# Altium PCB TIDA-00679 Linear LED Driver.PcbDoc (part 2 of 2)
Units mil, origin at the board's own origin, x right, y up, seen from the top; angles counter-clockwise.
Board outline 4400 x 2430 mil, 2 copper layers (Top Layer, Bottom Layer), stack 62 mil thick; 157 components, 72 nets, 421 pads, 393 vias.
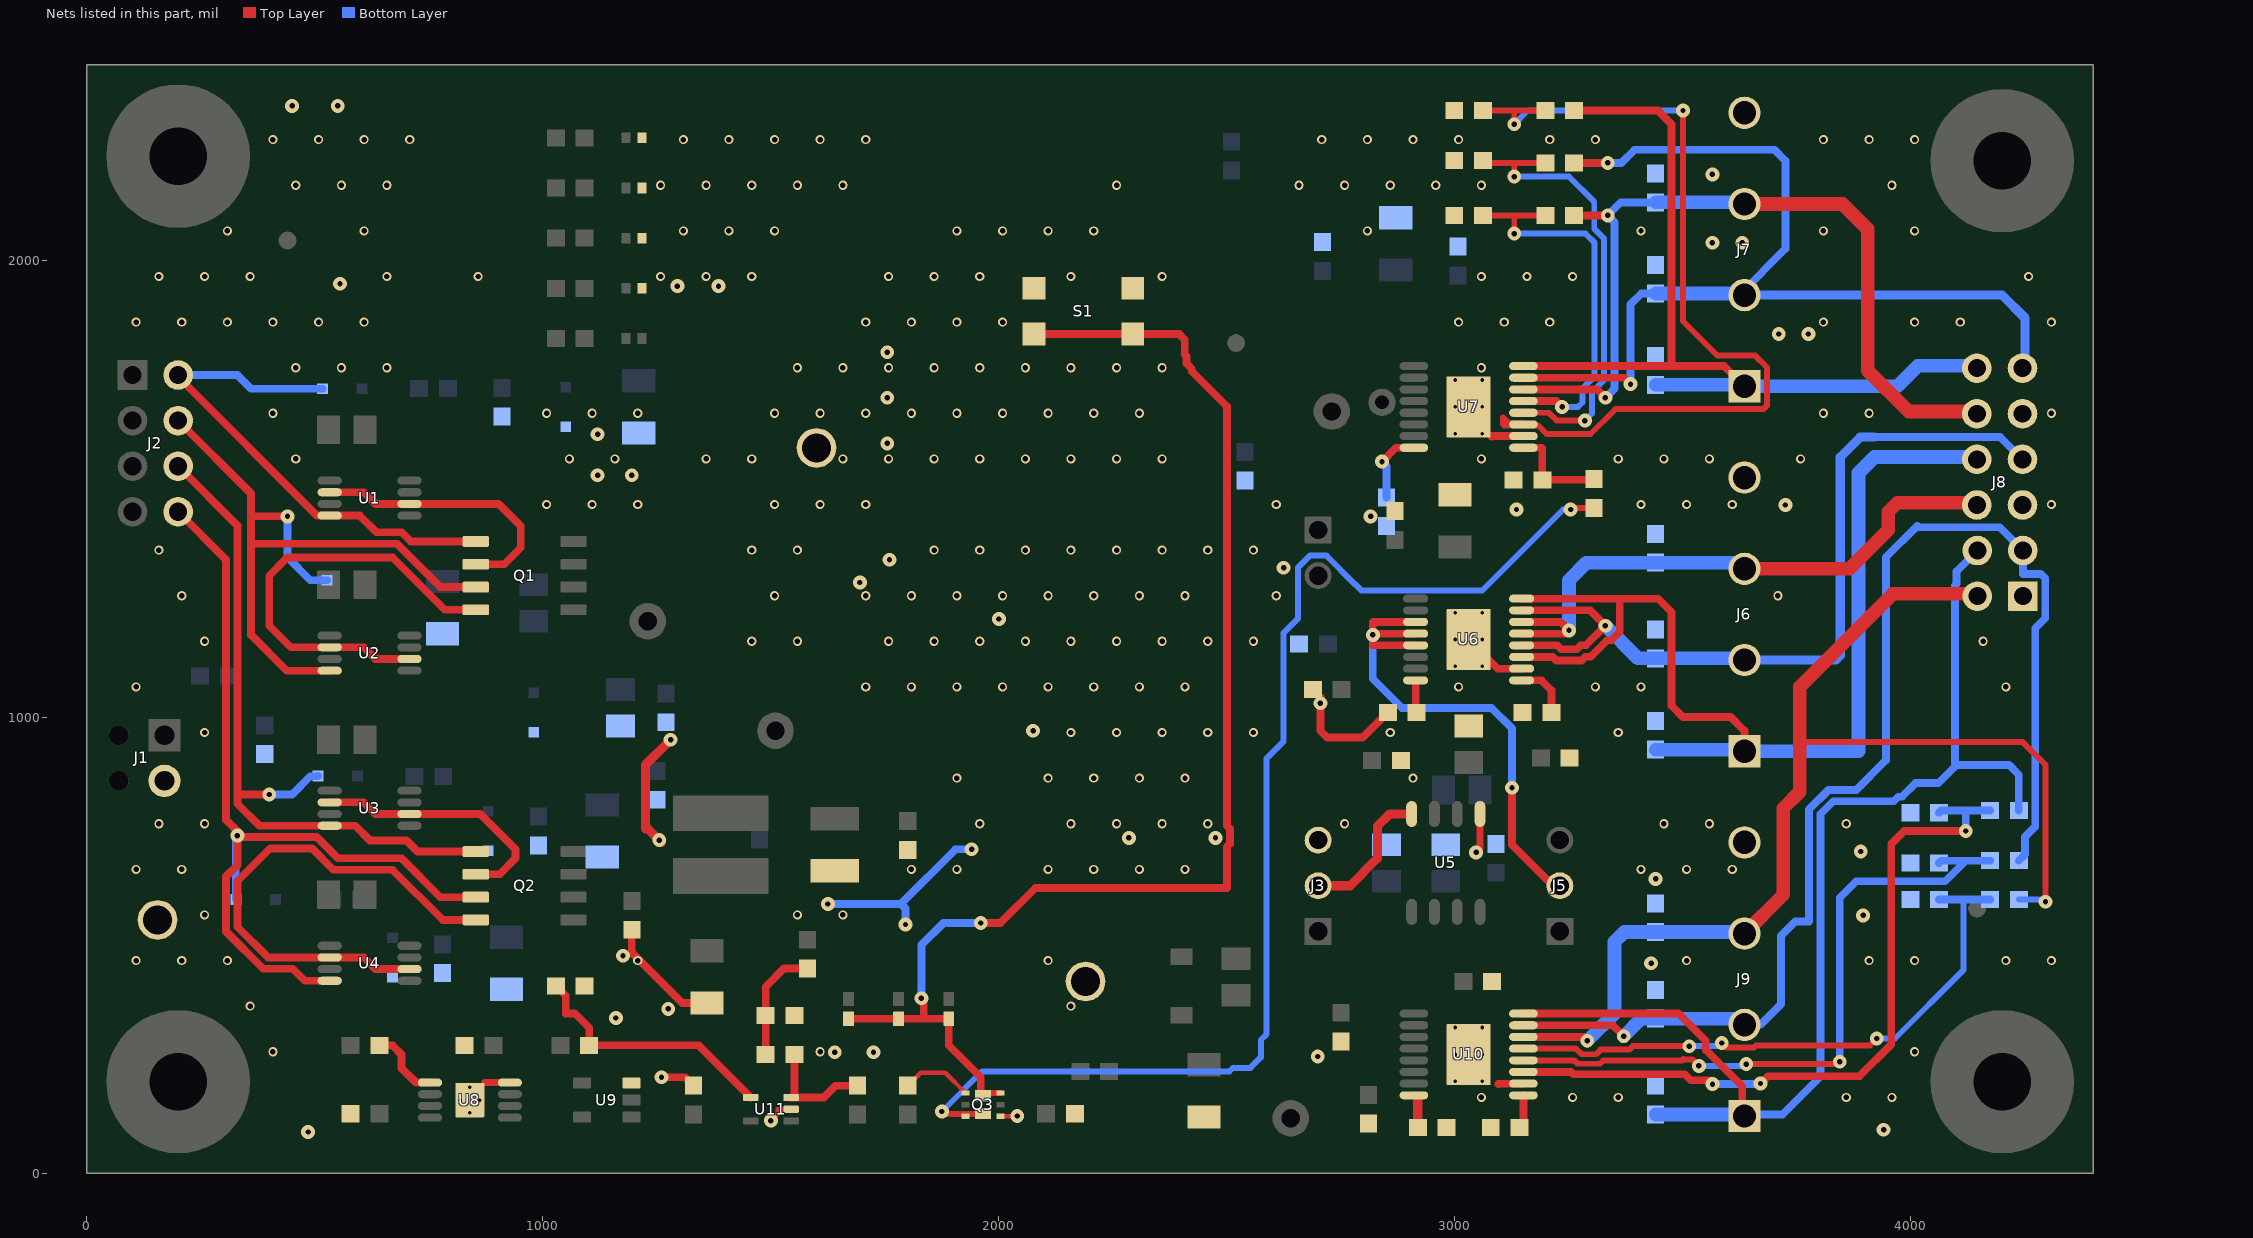
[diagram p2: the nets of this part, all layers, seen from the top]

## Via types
v1: diameter 20, hole 12, Top Layer to Bottom Layer, tented both sides, 246 vias
v2: diameter 30.32, hole 11.81, Top Layer to Bottom Layer, tented both sides, 123 vias
v3: diameter 15.75, hole 7.87, Top Layer to Bottom Layer, 18 vias
v4: diameter 19.68, hole 7.87, Top Layer to Bottom Layer, 4 vias
v5: diameter 30.32, hole 11.81, Top Layer to Bottom Layer, 2 vias

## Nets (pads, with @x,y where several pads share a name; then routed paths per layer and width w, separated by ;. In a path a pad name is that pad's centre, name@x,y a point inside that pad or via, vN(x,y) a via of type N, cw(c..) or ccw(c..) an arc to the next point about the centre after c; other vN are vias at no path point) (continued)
NetJ3_2: J3.2 U5.4 | length 311.2
  Top Layer w20: J3.2@2700,630 2770,630 2830,690 2830,760 2857.28,787.28 U5.4@2905,787.28
NetJ5_2: J5.2 U6.3 U6.4 U6.5 | length 1175.9
  Top Layer w17: U6.5@2913.86,1157.2 2820,1157.2 v2(2820,1180) v2@2820,1182.8 ; U6.4@2913.86,1182.8 v2@2820,1182.8 ; U6.3@2913.86,1208.39 2820.72,1208.39 2820,1207.67 v2@2820,1182.8 ; v2(3125,845) 3125,720 3215,630 J5.2@3230,630
  Bottom Layer w17: v2(2820,1180) 2820,1083.7 2883.7,1020 3080,1020 3125,975 v2(3125,845)
NetQ1_2: Q1.2 U1.2 U1.6 | length 610.5
  Top Layer w17: U1.2@532.4,1492.8 607.2,1492.8 632.8,1467.2 U1.6@707.6,1467.2 902.8,1467.2 951.14,1418.86 951.14,1371.14 915,1335 Q1.2@852.72,1335
NetQ1_4: Q1.4 U2.2 U2.6 | length 964.7
  Top Layer w17: U2.6@707.6,1127.2 632.8,1127.2 607.2,1152.8 U2.2@532.4,1152.8 447.2,1152.8 400,1200 400,1310 440,1350 670,1350 785,1235 Q1.4@852.72,1235
NetQ2_2: Q2.2 U3.2 U3.6 | length 572
  Top Layer w17: U3.2@532.4,812.8 607.2,812.8 632.8,787.2 U3.6@707.6,787.2 862.8,787.2 940,710 940,690 905,655 Q2.2@852.72,655
NetQ2_4: Q2.4 U4.2 U4.6 | length 1133.5
  Top Layer w17: U4.6@707.6,447.2 632.8,447.2 607.2,472.8 U4.2@532.4,472.8 397.2,472.8 330,540 330,640 401.87,711.87 493.57,711.87 540.31,665.13 670,665.13 780.13,555 Q2.4@852.72,555
NetQ3_6: Q3.6 Q3.7 R20.1 | length 2724.5
  Top Layer w13: v2(1875,135) 1880.87,129.13 1965,129.13 Q3.7@1965,130.79 ; v2(3253.7,1455) 3257.2,1458.5 R20.1@3305,1458.5
  Bottom Layer w13: v2@1870,140 v2(1875,135) 1962.97,222.97 2505.63,222.97 2513.28,230.63 2551.31,230.63 2574.37,253.69 2574.37,291.72 2587.13,304.47 2587.13,909.47 2624.44,946.79 2624.44,1184.65 2656.1,1216.31 2656.1,1328.18 2681.82,1353.9 2718.18,1353.9 2780.63,1291.46 2781.19,1291.46 2795.53,1277.13 3059.47,1277.13 3237.35,1455 v2(3253.7,1455)
NetR16_2: R16.2 U6.8 | length 71.3
  Top Layer w17: U6.8@2913.86,1080.43 2913.86,1012.07 R16.2@2915.92,1010
NetR17_2: R17.2 U7.8 | length 169.1
  Top Layer w17: v2(2840,1560) 2870.43,1590.43 U7.8@2913.86,1590.43
  Bottom Layer w17: v2(2840,1560) 2850,1550 R17.2@2850,1481.5
NetR18_2: R18.2 U6.9 | length 122.9
  Top Layer w17: U6.9@3146.14,1080.43 3189.57,1080.43 3211.5,1058.5 R18.2@3211.5,1010
NetR19_2: R19.2 R20.2 U7.9 | length 226.9
  Top Layer w17: U7.9@3146.14,1590.43 3190,1590.43 3191.5,1588.94 R19.2@3191.5,1520 R20.2@3303.5,1520
NetR21_1: R21.1 R22.2 U7.13 | length 861.9
  Top Layer w13: R22.2@3061.5,2100 3130,2100 ; v2(3130,2060) 3130,2100 ; R21.1@3198.5,2100 3130,2100
  Top Layer w17: U7.13@3150.08,1692.8 3222.2,1692.8 v2(3235,1680)
  Bottom Layer w13: v2(3130,2060) 3286.42,2060 3306.25,2040.16 3306.25,1747.54 3279.59,1720.88 3279.59,1689.59 3270,1680 v2(3235,1680)
NetR23_1: R23.1 R24.2 U7.12 | length 1015.5
  Top Layer w13: R24.2@3061.5,2220 3066.5,2215 3130,2215 ; v2(3130,2185) 3130,2215 ; U7.12@3150.08,1667.2 3206.03,1667.2 3222.77,1650.47 3284.53,1650.47 v2(3285,1650) ; R23.1@3198.5,2215 3130,2215
  Bottom Layer w13: v2(3130,2185) 3250,2185 3305.47,2129.53 3305.47,2070.47 3327.13,2048.81 3327.13,1738.89 3300.47,1712.23 3300.47,1665.47 v2(3285,1650)
NetR25_1: R25.1 R26.2 U7.11 | length 2006.6
  Top Layer w13: R26.2@3061.5,2330 3130,2330 ; v2(3130,2300) 3130,2330 ; U7.11@3150.08,1641.61 3152.44,1643.97 3117.82,1643.97 3104.82,1656.97 3104.82,1642.52 3108.08,1639.26 3182.34,1639.26 3201.13,1620.47 3297.23,1620.47 3351.96,1675.19 3676.18,1675.19 3684.6,1683.61 3684.6,1766.39 3658.54,1792.44 3575.77,1792.44 3500,1868.21 v2(3500,2330) ; R25.1@3198.5,2330 3130,2330
  Bottom Layer w13: v2(3130,2300) 3160,2330 v2(3500,2330)
NetR27_1: R27.1 U8.5 | length 162.3
  Top Layer w17: R27.1@641.5,280 670,280 690,260 690,230 721.61,198.39 U8.5@752.4,198.39
NetR32_1: R32.1 R33.2 R37.1 | length 256.6
  Top Layer w17: R37.1@1488.5,260 1488.5,350 1488.5,408.5 1528.5,448.5 R32.1@1580,448.5
NetR34_1: R34.1 R35.2 U11.4 | length 573.6
  Top Layer w17: R35.2@1028.5,410 1050,388.5 1050,350 1070,350 1101.5,318.5 R34.1@1101.5,280 1341.3,280 U11.4@1455.71,165.59
NetR36_2: R36.2 U10.8 | length 71.2
  Top Layer w20: U10.8@2913.86,169.29 2918.5,164.65 R36.2@2918.5,100
NetR37_2: R37.2 R39.2 U11.3 | length 253.8
  Top Layer w17: R37.2@1551.5,260 1551.5,172.8 U11.3@1544.29,165.59 1615.59,165.59 1641.5,191.5 R39.2@1690,191.5
NetR38_2: R38.2 U10.9 | length 74
  Top Layer w17: R38.2@3141.5,100 3150.08,108.58 U10.9@3150.08,170.43
NetR40_1: R40.1 R41.2 U10.13 | length 1321.6
  Top Layer w13: U10.13@3150.08,272.8 3265.44,272.8 3277.77,260.47 3309.53,260.47 3319.53,270.47 3382.23,270.47 3389.92,278.16 v2(3513.77,278.16) ; v2(3585,285) 3594.81,275.19 3655.42,275.19 3660.23,280 3910,280 v2(3925,295)
  Bottom Layer w13: v2(3513.77,278.16) 3578.16,278.16 v2(3585,285) ; v2(3925,295) 3965,295 4115,445 4115,600
  Bottom Layer w17: R41.2@4061.5,600 4115,600 R40.1@4173.5,600
NetR42_1: R42.1 R43.2 U10.12 | length 1494.6
  Top Layer w13: U10.12@3150.08,247.2 3261.51,247.2 3269.12,239.59 3318.18,239.59 3325.79,247.2 3498.18,247.2 3500.57,249.59 3501.53,248.63 3521.37,248.63 v2(3535,235) ; v2(3638.89,238.89) 3838.89,238.89 v2(3843.89,243.89)
  Bottom Layer w13: v2(3535,235) 3635,235 v2(3638.89,238.89)
  Bottom Layer w17: v2(3843.89,243.89) 3843.89,603.89 3880,640 4075,640 4120,685 ; R43.2@4061.5,680 4066.5,685 4120,685 ; R42.1@4173.5,685 4120,685
NetR44_1: R44.1 R45.2 U10.11 | length 1627.4
  Top Layer w17: U10.11@3150.08,221.61 3254.75,221.61 3259.65,216.72 3503.79,216.72 3517.05,203.47 3556.36,203.47 v2(3564.75,195.08) ; v2(3669.97,196.21) 3686.12,212.36 3886.95,212.36 3956.53,281.94 3956.53,721.53 3985,750 v2(4120,750)
  Bottom Layer w17: v2(3564.75,195.08) 3668.84,195.08 v2(3669.97,196.21) ; R45.2@4061.5,790 4066.5,795 4120,795 ; v2(4120,750) 4120,795 ; R44.1@4173.5,795 4120,795
RESET: D15.1 D16.1 D17.1 Q3.3 Q3.8 S1.3 S1.4 | length 2920.6
  Top Layer w13: Q3.8@1960,179.29 1963.7,175.59 Q3.3@2003.39,175.59
  Top Layer w17: D15.1@1670,338.35 D16.1@1780,338.35 1835,338.35 ; v2(1830,383.35) 1835,378.35 1835,338.35 ; Q3.8@1960,179.29 1960,210 1890,280 D17.1@1890,338.35 1835,338.35 ; v2(1960,548.35) 2003.17,548.35 2079.7,624.87 2499.87,624.87 2499.87,715.28 2506.53,721.94 2506.53,754.72 2499.87,761.38 2499.87,1681.27 2422.72,1758.42 2422.72,1763.83 2411.5,1775.06 2411.5,1790.93 2407.67,1794.75 2407.67,1827.33 2395,1840 S1.4@2293.27,1840 S1.3@2076.73,1840
  Bottom Layer w17: v2(1830,383.35) 1830,500 1878.35,548.35 v2(1960,548.35)
REV1: C47.2 J8.4 J9.1 R44.2 U10.16 | length 2671.8
  Top Layer w17: U10.16@3146.14,349.57 3490.43,349.57 3550,290 3550,270 3630,190 J9.1@3630,110
  Bottom Layer w17: J9.1@3626.39,128.5 3718.5,128.5 3801.4,211.4 3801.4,787.05 3829.48,815.13 3962.09,815.13 3972.04,825.07 3980.07,825.07 4010,855 4060,855 4100,895 ; J8.4@4145.5,1365 4100,1319.5 4100,1291.94 4096.65,1288.59 4096.65,898.35 4100,895 ; R44.2@4236.5,795 4236.5,873.5 4215,895 4100,895
  Bottom Layer w30: C47.2@3440.07,128.5 J9.1@3626.39,128.5
REV2: C45.2 J8.3 J9.2 R42.2 U10.15 | length 2846.2
  Top Layer w17: U10.15@3146.14,323.98 3346.02,323.98 v2(3370,300)
  Bottom Layer w17: J9.2@3634.79,325 3670,325 3715,370 3715,520.33 3746.19,551.52 3776.52,551.52 3776.52,797.35 3819.17,840 3880,840 3945,905 3945,1350 4013.85,1418.85 4016.56,1416.15 4194.35,1416.15 J8.3@4245.5,1365 4245.5,1313.85 4284.76,1313.85 4294.35,1304.26 4294.35,1216.65 4272.56,1194.85 4272.56,759.93 4250,737.37 4250,698.5 R42.2@4236.5,685
  Bottom Layer w30: v2(3370,300) 3408.5,338.5 C45.2@3440.07,338.5 3621.29,338.5 J9.2@3634.79,325
REV3: C43.2 J8.2 J9.3 R40.2 U10.14 | length 2691.9
  Top Layer w13: 3756.37,945 4245,945 4295,895 v2(4295,595)
  Top Layer w17: U10.14@3146.14,298.39 U10.14@3150.08,298.39 3281.61,298.39 v2(3290,290)
  Top Layer w30: J9.3@3634.79,525 3720,610.21 3720,800 3756.37,836.37 3756.37,945 3756.37,1066.37 3960,1270 4140.5,1270 J8.2@4145.5,1265
  Bottom Layer w13: R40.2@4236.5,600 4290,600 v2(4295,595)
  Bottom Layer w30: v2(3290,290) 3350,350 3350,507.01 3371.5,528.5 C43.2@3440.07,528.5 J9.3@3611.5,528.5 ; J9.3@3630,510 J9.3@3611.5,528.5 ; J9.3@3630,530 cw(c3626.39,533.61) 3626.39,528.5 J9.3@3611.5,528.5
REVGND: C1.1 C7.2 C8.2 C9.2 C10.2 C11.2 C12.1 C13.1 C14.1 C15.2 C16.1 C17.2 C18.1 C19.1 C20.2 C21.1 C22.2 C23.2 C24.1 C25.1 C26.2 C27.2 C28.2 C29.1 C30.1 C31.1 C32.1 C33.1 C34.1 C35.2 C36.1 C37.2 C38.1 C39.2 C40.1 C41.2 C42.1 C43.1 C44.1 C45.1 C46.1 C47.1 D4.1 D6.2 D7.1 D8.2 D9.1 D10.2 D12.1 D13.2 GND_1.1 GND_2.1 GND_3.1 J1.2 J3.3 J6.4 J7.4 J8.1 J8.5 J8.9 J9.4 Q3.1 Q3.4 R8.1 R10.1 R14.1 R15.1 R16.1 R17.1 R18.1 R19.1 R22.1 R24.1 R26.1 R30.1 R33.1 R35.1 R36.1 R38.1 R41.1 R43.1 R45.1 S1.1 S1.2 U5.1 U6.10 U6.17 U7.10 U7.17 U8.4 U8.9 U9.3 U10.10 U10.17 U11.2 | length 1971.7
  Top Layer w10: v2@1500,125 v2(1500,115) 1515,130 1515,140 U11.2@1544.29,140 ; C46.1@1800,191.5 1828.5,220 1882.2,220 Q3.4@1926.61,175.59 ; Q3.1@2003.39,124.41 2039.41,124.41 v2(2040,125)
  Top Layer w15: 871.61,198.39 U8.4@931.54,198.39 ; v2(3046.3,703.19) 3055,711.89 U5.1@3055,787.28
  Top Layer w17: C7.2@1195,533.5 1195,483.5 1305.59,372.91 C8.2@1360,372.91 ; v2(1260,210) 1311.5,210 C37.2@1330,191.5 ; C22.2@2688.5,1060 2705,1043.5 v2(2705,1030) 2705,970 2720,955 2797.93,955 R16.1@2852.93,1010 ; U6.17@3030,1170 3093.98,1106.02 U6.10@3146.14,1106.02 ; 3080,1615 3081.02,1616.02 U7.10@3150.08,1616.02 ; 3095,195 3096.02,196.02 U10.10@3150.08,196.02
  Top Layer w20: v2@1260,725 v2(1255,730) 1230,755 1225,755 1225,895 v2(1280,950)
  Bottom Layer w17: v2(1625,590) 1785,590 ; v2(1795,545) 1795,580 1785,590 ; v2(1940,710) 1905,710 1785,590
  other v1: 3058,166 3258,166 3358,166 3858,166 3958,166 408,266 1608,266 4008,266 358,366 2158,366 108,466 208,466 308,466 1208,466 2108,466 3508,466 3908,466 4008,466 4208,466 4308,466 258,566 1558,566 1658,566 108,666 208,666 1808,666 1908,666 2108,666 2208,666 2308,666 2408,666 3408,666 3508,666 3608,666 158,766 258,766 1958,766 2158,766 2258,766 2358,766 2458,766 2758,766 3458,766 3558,766 3858,766 1908,866 2108,866 2208,866 2308,866 2408,866 2908,866 258,966 2158,966 2258,966 2358,966 2458,966 2558,966 2858,966 3358,966 108,1066 1708,1066 1808,1066 1908,1066 2008,1066 2108,1066 2208,1066 2308,1066 2408,1066 3008,1066 3308,1066 3408,1066 4208,1066 258,1166 1458,1166 1558,1166 1758,1166 1858,1166 1958,1166 2058,1166 2158,1166 2258,1166 2358,1166 2458,1166 2558,1166 4158,1166 208,1266 1508,1266 1708,1266 1808,1266 1908,1266 2008,1266 2108,1266 2208,1266 2308,1266 2408,1266 2608,1266 3708,1266 158,1366 1458,1366 1558,1366 1858,1366 1958,1366 2058,1366 2158,1366 2258,1366 2358,1366 2458,1366 2558,1366 1008,1466 1108,1466 1208,1466 1508,1466 1608,1466 1708,1466 2608,1466 3408,1466 3508,1466 3608,1466 4308,1466 458,1566 1058,1566 1158,1566 1358,1566 1458,1566 1658,1566 1758,1566 1858,1566 1958,1566 2058,1566 2158,1566 2258,1566 2358,1566 3058,1566 3358,1566 3458,1566 3558,1566 3758,1566 408,1666 1008,1666 1108,1666 1208,1666 1508,1666 1608,1666 1708,1666 1808,1666 1908,1666 2008,1666 2108,1666 2208,1666 2308,1666 3808,1666 3908,1666 4308,1666 458,1766 558,1766 658,1766 1558,1766 1658,1766 1758,1766 1858,1766 1958,1766 2058,1766 2158,1766 2258,1766 2358,1766 3058,1766 108,1866 208,1866 308,1866 408,1866 508,1866 608,1866 1708,1866 1808,1866 1908,1866 2008,1866 3008,1866 3108,1866 3208,1866 3808,1866 4008,1866 4108,1866 4308,1866 158,1966 258,1966 358,1966 658,1966 858,1966 1258,1966 1358,1966 1458,1966 1758,1966 1858,1966 1958,1966 2158,1966 2358,1966 3058,1966 3158,1966 3258,1966 4258,1966 308,2066 608,2066 1308,2066 1408,2066 1508,2066 1908,2066 2008,2066 2108,2066 2208,2066 2808,2066 3408,2066 3808,2066 4008,2066 458,2166 558,2166 658,2166 1258,2166 1358,2166 1458,2166 1558,2166 1658,2166 2258,2166 2658,2166 2758,2166 2858,2166 2958,2166 3058,2166 3958,2166 408,2266 508,2266 608,2266 708,2266 1308,2266 1408,2266 1508,2266 1608,2266 1708,2266 2708,2266 2808,2266 2908,2266 3008,2266 3208,2266 3308,2266 3808,2266 3908,2266 4008,2266
  other v2: 485,90 3940,95 2699.13,255.49 1640,265 1725,265 1160,340 1275,360 1175.57,476.35 3895,565 3890,705 2285,735 2475,735 2075,970 2000,1215 1695,1295 2624.33,1327.47 1760,1345 2815,1440 3135,1455 3724.67,1465 1120,1530 1195,1530 1755,1600 1120,1620 1755,1700 1755,1800 3710,1840 3775,1840 1295,1945 1385,1945 555,1950 3564.5,2040 3630,2040 3564.5,2190 450,2340 550,2340
  other v3: 3000.47,200.94 3059.53,200.94 3000.47,260 3059.53,260 3000.47,319.06 3059.53,319.06 3000.47,1110.94 3059.53,1110.94 3000.47,1170 3059.53,1170 3000.47,1229.06 3059.53,1229.06 3000.47,1620.94 3059.53,1620.94 3000.47,1680 3059.53,1680 3000.47,1739.06 3059.53,1739.06
  other v4: 840,132.05 818.35,160 861.65,160 840,187.95
  other v5: 3430.06,460 3440,645
TB1: C34.2 J7.1 J8.12 R25.2 U7.16 | length 2009.5
  Top Layer w17: U7.16@3146.14,1769.57 U7.16@3150.08,1769.57 3475,1769.57 ; R25.2@3261.5,2330 3445,2330 3475,2300 3475,1769.57 ; J7.1@3630,1710 3630,1730 3590.43,1769.57 3475,1769.57
  Bottom Layer w30: C34.2@3440,1728.5 J7.1@3621.5,1728.5 ; J7.1@3630,1720 J7.1@3621.5,1728.5 ; J7.1@3630,1730 cw(c3626.39,1733.61) 3626.39,1728.5 J7.1@3621.5,1728.5 ; J7.1@3634.79,1725 3970,1725 4015,1770 4139.5,1770 J8.12@4144.5,1765
TB2: C32.2 J7.2 J8.11 R23.2 U7.15 | length 2263.2
  Top Layer w17: U7.15@3150.08,1743.98 3371.02,1743.98 v2(3385,1730) ; R23.2@3261.5,2215 v2(3335,2215)
  Bottom Layer w17: v2(3335,2215) 3365,2215 3393.87,2243.87 3700.8,2243.87 3724.67,2220 3724.67,2026.78 J7.2@3626.39,1928.5 ; v2(3385,1730) 3385,1905 3408.5,1928.5 C32.2@3440.07,1928.5
  Bottom Layer w20: J7.2@3634.79,1925 4200,1925 4250,1875 4250,1770.5 J8.11@4244.5,1765
  Bottom Layer w30: C32.2@3440.07,1928.5 J7.2@3611.5,1928.5 ; J7.2@3624.89,1915.11 J7.2@3611.5,1928.5 ; J7.2@3626.39,1928.5 J7.2@3621.5,1928.5 ; J7.2@3630,1920 J7.2@3621.5,1928.5 ; J7.2@3611.5,1928.5 J7.2@3621.5,1928.5
TB3: C30.2 J7.3 J8.10 R21.2 U7.14 | length 1906.2
  Top Layer w17: U7.14@3150.08,1718.39 3311.61,1718.39 v2(3330,1700) ; R21.2@3261.5,2100 v2(3335,2100)
  Top Layer w30: J7.3@3634.79,2125 3850,2125 3905,2070 3905,1760 3995,1670 J8.10@4150,1670
  Bottom Layer w17: v2(3330,1700) 3350,1720 3350,2085 v2(3335,2100) 3363.5,2128.5 C30.2@3440.07,2128.5
  Bottom Layer w30: C30.2@3440.07,2128.5 J7.3@3611.5,2128.5 ; J7.3@3630,2110 J7.3@3611.5,2128.5 ; J7.3@3630,2120 J7.3@3621.5,2128.5 ; J7.3@3630,2130 cw(c3626.39,2133.61) 3626.39,2128.5 J7.3@3621.5,2128.5 ; J7.3@3611.5,2128.5 J7.3@3621.5,2128.5
TURN1: C33.2 J6.1 J8.8 U6.11 U6.16 | length 2466.8
  Top Layer w17: U6.11@3146.14,1131.61 3214.7,1131.61 3222.56,1123.75 3277.44,1123.75 3286.02,1132.33 3297.51,1132.33 3333.65,1168.47 3343.06,1168.47 3361.53,1186.94 3361.53,1256.1 3365,1259.57 ; U6.16@3146.14,1259.57 3365,1259.57 ; J6.1@3619.79,910 J6.1@3634.79,925 3634.79,970.21 3604.87,1000.13 3499.7,1000.13 3475.13,1024.7 3475.13,1229.87 3445.43,1259.57 3365,1259.57
  Bottom Layer w30: C33.2@3440.07,928.5 J6.1@3611.5,928.5 ; J6.1@3630,910 J6.1@3611.5,928.5 ; J6.1@3630,930 cw(c3626.39,933.61) 3626.39,928.5 J6.1@3611.5,928.5 ; J6.1@3634.79,925 3885,925 3885,1535 3920,1570 4139.5,1570 J8.8@4144.5,1565
TURN2: C31.2 J6.2 J8.7 U6.12 U6.15 | length 1842.8
  Top Layer w17: U6.12@3146.14,1157.2 3224.28,1157.2 3232.86,1148.63 3267.14,1148.63 3275.72,1157.2 3287.2,1157.2 v2(3330,1200) 3296.02,1233.98 U6.15@3146.14,1233.98
  Bottom Layer w17: 3919.48,1613.85 4195.65,1613.85 J8.7@4244.5,1565
  Bottom Layer w20: J6.2@3634.79,1125 3835,1125 3845,1135 3845,1570 3888.85,1613.85 3919.48,1613.85
  Bottom Layer w30: v2(3330,1200) 3401.5,1128.5 C31.2@3440.07,1128.5 J6.2@3611.5,1128.5 ; J6.2@3624.89,1115.11 J6.2@3611.5,1128.5 ; J6.2@3630,1130 cw(c3626.39,1133.61) 3626.39,1128.5 J6.2@3611.5,1128.5
TURN3: C29.2 J6.3 J8.6 U6.13 U6.14 | length 1329.9
  Top Layer w17: U6.13@3146.14,1182.8 3242.8,1182.8 v2(3250,1190) 3231.61,1208.39 U6.14@3146.14,1208.39
  Top Layer w30: J6.3@3634.79,1325 3865,1325 3950,1410 3950,1450 3970,1470 4139.5,1470 J8.6@4144.5,1465
  Bottom Layer w30: v2(3250,1190) 3250,1300 3288.5,1338.5 C29.2@3440.07,1338.5 3621.29,1338.5 J6.3@3634.79,1325
"VIN 1": D3.2 J2.2 Q1.1 U1.4 | length 1135.2
  Top Layer w17: J2.2@200,1750 200,1746.21 504.23,1441.97 532.04,1441.97 U1.4@532.4,1441.61 598.39,1441.61 635.13,1404.87 690.3,1404.87 710.18,1385 Q1.1@852.72,1385
  Bottom Layer w17: J2.2@200,1750 330,1750 360,1720 D3.2@516.69,1720
"VIN 2": D5.2 J2.4 Q1.3 U2.4 | length 1550.6
  Top Layer w17: J2.4@200,1650 360,1490 360,1440 ; v2(440,1440) 360,1440 ; U2.4@532.4,1101.61 438.39,1101.61 360,1180 360,1380 ; Q1.3@852.72,1285 775,1285 680,1380 360,1380 ; 360,1380 360,1440
  Bottom Layer w17: v2(440,1440) 440,1350 490,1300 D5.2@526.69,1300
"VIN 3": D2.2 J2.6 Q2.1 U3.4 | length 1553.7
  Top Layer w17: J2.6@200,1550 330,1420 330,830 ; v2(400,830) 330,830 ; Q2.1@852.72,705 725,705 700.87,729.13 620.87,729.13 588.39,761.61 U3.4@532.4,761.61 378.39,761.61 330,810 330,830
  Bottom Layer w17: v2(400,830) 450,830 489.96,869.96 505.79,869.96 D2.2@506.69,870.87
"VIN 4": D11.2 J2.8 Q2.3 U4.4 | length 1976.5
  Top Layer w17: J2.8@200,1450 305.13,1344.87 305.13,774.82 330,749.95 v2(330,740) ; U4.4@532.4,421.61 477.98,421.61 451.67,447.92 386.9,447.92 305.13,529.7 305.13,650.3 330,675.18 v2(330,740) ; Q2.3@852.72,605 775,605 690,690 550.62,690 503.88,736.74 333.26,736.74 v2(330,740)
  Bottom Layer w17: D11.2@326.69,600 326.69,736.69 v2(330,740)
pads on no net: FID1.1 FID2.1 FID3.1 H1.0 H2.1 H3.0 H4.1 H5.0 H6.1 H7.0 H8.1 J1.MH1 J1.MH2 U1.3 U1.5 U2.3 U2.5 U3.3 U3.5 U4.3 U4.5 U8.2 U8.3 U8.6 U8.7 U9.1

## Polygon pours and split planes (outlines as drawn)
NetC7_1 on Top Layer "Top Layer-No Net" (solid, remove dead copper, pour order 10): 1031.69,1406.46 1035.24,1410 1270,1410 1320,1360 1330,1350 1330,1170 1270,1110 1200,1110 1170,1080 1170,860 1170,746.26 1176.26,740 1216.26,700 1230,700 1493.03,700 1494.33,701.3 1520,675.63 1520,630 1520,470 1500,450 1290,450 1290,460 1250,500 1090,500 1060,500 1020,540
KL30_F on Top Layer "Top Layer-No Net 1" (solid, remove dead copper, pour order 5): 1288.03,828 1289.61,826.43 1289.61,750 1690,750 1695,755 1690,760 1690,805 1585,805 1560,830 1515,830 1290.03,830 1288.03,828
REVGND on Top Layer "Top Layer-No Net 3" (solid, remove dead copper, pour order 9): 0,2430 4400,2430 4400,0 0,0 0,2430
REVGND on Bottom Layer "Bottom Layer-No Net" (solid, remove dead copper, pour order 11): 0,2430 4400,2430 4400,0 5,0 0,-5 0,2430

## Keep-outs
Keep-Out Layer:
  the board outline again, w10
  text ".Layer_Name" at 577,-858.49 h60

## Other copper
Top Layer:
  text ".Layer_Name" at 577,-858.49 h60
Bottom Layer:
  text ".Layer_Name" at 577,-858.49 h60

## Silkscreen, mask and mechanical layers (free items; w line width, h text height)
Top Overlay:
  lines w10: 660,1760 1820,1760 1820,2340 660,2340 660,1760
  text "GND" at 3880,2285 h40 r90
  text "TAIL LIGHT" at 1290,2250 h40
  text "BRAKE LIGHT" at 1290,2140 h40
  text "OU|T3" at 3885,2080 h40 r90
  text "TURN LIGHT" at 1290,2030 h40
  text "REVERSE LIGHT" at 1290,1920 h40
  text "LINEAR" at 175,1915 h40
  text "OUT2" at 3885,1900 h40 r90
  text "VERSION" at 360,1855 h40
  text "2" at 4135,1850 h40
  text "1" at 4250,1850 h40
  text "TAIL/BREAK" at 3995,1845 h40 r90
  text "FAULT" at 1290,1810 h40
  text "FAULT" at 2060,1735 h31.5
  text "TAIL" at 280,1730 h40
  text "OUT1" at 3890,1700 h40 r90
  text "RESTART" at 2060,1680 h31.5
  text "BRAKE" at 275,1635 h40
  text "TURN" at 275,1525 h40
  text "GND" at 3890,1500 h40 r90
  text "REAR" at 270,1420 h40
  text "FAULT" at 2385,1400 h40
  text "OUT3" at 3890,1295 h40 r90
  text "FAULT_S" at 2360,1290 h40
  text "TURN" at 4000,1170 h40 r90
  text "12" at 4125,1160 h40
  text "11" at 4240,1160 h40
  text "OUT2" at 3890,1100 h40 r90
  text "VIN" at 55,1040 h40
  text "+" at 330,965 h40
  text "TIDA-00679" at 1765,965 h60
  text ".PCB_Rev" at 2365,965 h60
  text "OUT1" at 3895,900 h40 r90
  text "-" at 330,845 h40
  text "OFF" at 2520,710 h40
  text "GND" at 3900,700 h40 r90
  text "ON" at 3340,660 h40 r90
  text "OSC" at 2510,600 h40
  text "BLINK" at 3170,540 h40 r90
  text "OFF" at 3340,510 h40 r90
  text "OUT3" at 3905,500 h40 r90
  text "ON" at 2560,495 h40
  text "REAR" at 4005,450 h40 r90
  text "OUT2" at 3905,300 h40 r90
  text "OUT1" at 3905,100 h40 r90
  text ".Layer_Name" at 577,-858.49 h60
Bottom Overlay:
  text ".Layer_Name" at 577,-858.49 h60
Top Paste:
  text ".Layer_Name" at 577,-858.49 h60
Bottom Paste:
  text ".Layer_Name" at 577,-858.49 h60
Top Solder:
  text ".Layer_Name" at 577,-858.49 h60
  text ".Layer_Name" at 577,-858.49 h60
Bottom Solder:
  text ".Layer_Name" at 577,-858.49 h60
Drill Guide:
  text ".Layer_Name" at 577,-858.49 h60
M1 Board Outline:
  lines w10: -6260,340 -1860,340 ; 0,0 0,2430 4400,2430 4400,0 0,0
  text ".Layer_Name" at 577,-858.49 h60
M2 Board Dimensions:
  rectangle: 0,-275 125,-150
  rectangle: 125,-400 500,-275
  lines w7: 0,-275 1000,-275 ; 125,-400 125,-150 ; 250,-400 250,-150 ; 500,-400 500,-150 ; 750,-400 750,-150 ; 0,-400 1000,-400 1000,-150 0,-150 0,-400
  text ".Layer_Name" at 577,-858.49 h60
M3 3D STEP Top:
  text ".Layer_Name" at 577,-858.49 h60
M4 3D STEP Bottom:
  text ".Layer_Name" at 577,-858.49 h60
M5 Assembly Top:
  lines w10: -292,-930.17 6308,-930.17 ; -292,-726.83 6310,-726.83 ; -292,-523.5 -292,-1133.5 3713,-1133.5 6310,-1133.5 6310,-523.5 -291.5,-523.5 -291.5,-1133.5 1284,-1133.5 ; 2173,-1133.5 2173,-523.5 ; 3440,-726.83 3440,-523.5 ; 4280,-726.83 4280,-523.5 ; 4902,-1140 4902,-937.17
  text "COMPONENTS MARKED 'DNP' SHOULD NOT BE POPULATED." at 1153.5,-318.5 h60
  text "ASSEMBLY VARIANT:" at 1153,-434 h60
  text ".VariantName" at 2189,-434 h60
  text "PCB VIEWED FROM TOP SIDE" at -228.5,-655.67 h60
  text "BOARD #:" at 2248,-655.67 h60
  text ".PRJ_Number" at 2793.5,-655.67 h60
  text "REV:" at 3638,-655.67 h60
  text ".PCB_Rev" at 3929.5,-655.67 h60
  text "SVN REV:" at 4476,-655.67 h60
  text ".VersionControl_RevNumber" at 4982,-655.67 h60
  text "TID #:" at 2248,-859 h60
  text ".TID" at 2793.5,-859 h60
  text "PLOT NAME =" at -228.5,-1064.34 h60
  text ".plot_File_Name" at 577,-1064.34 h60
  text "GENERATED    :" at 2250,-1064.34 h60
  text ".Print_Date" at 3119.5,-1064.34 h60
  text ".Print_Time" at 3848.5,-1064.34 h60
  text "TEXAS INSTRUMENTS" at 5113,-1064.34 h60
M6 Assembly Bottom:
  lines w10: -292.5,-727.33 6309.5,-727.33 ; -290.5,-930.67 6309.5,-930.67 ; 1115.5,-1140.5 1115.5,-937.67 ; 1737.5,-727.33 1737.5,-524 ; 2577.5,-727.33 2577.5,-524 ; 3844.5,-1134 3844.5,-524 ; 4733.5,-1134 6309,-1134 6309,-524 -292.5,-524 -292.5,-1134 2304.5,-1134 6309.5,-1134 6309.5,-524
  text "COMPONENTS MARKED 'DNP' SHOULD NOT BE POPULATED." at 6102,-318 h60
  text ".VariantName" at 5058,-434 h60
  text "ASSEMBLY VARIANT:" at 6097,-434 h60
  text ".VersionControl_RevNumber" at 1035.5,-656.17 h60
  text "SVN REV:" at 1541.5,-656.17 h60
  text ".PCB_Rev" at 2088,-656.17 h60
  text "REV:" at 2379.5,-656.17 h60
  text ".PRJ_Number" at 3224,-656.17 h60
  text "BOARD #:" at 3769.5,-656.17 h60
  text "PCB VIEWED FROM BOTTOM SIDE" at 6246,-656.17 h60
  text ".TID" at 3224,-859.5 h60
  text "TID #:" at 3769.5,-859.5 h60
  text "TEXAS INSTRUMENTS" at 904.5,-1064.84 h60
  text ".Print_Time" at 2169,-1064.84 h60
  text ".Print_Date" at 2898,-1064.84 h60
  text "GENERATED    :" at 3767.5,-1064.84 h60
  text ".plot_File_Name" at 5440.5,-1064.84 h60
  text "PLOT NAME =" at 6246,-1064.84 h60
M9 Title Sheet:
  drawing of 57 lines, arcs and shapes, not listed
  text "1" at 739.84,8036.5 h70
  text "2" at 3235.5,8036.5 h70
  text "3" at 5724.84,8036.5 h70
  text "4" at 8231.51,8036.5 h70
  text "5" at 10730.5,8036.5 h70
  text "6" at 13235.5,8036.5 h70
  text "A" at -416.5,6893.5 h70
  text "A" at 14383.5,6893.5 h70
  text "B" at -416.5,4513.5 h70
  text "B" at 14383.5,4513.5 h70
  text "C" at -416.5,2138.5 h70
  text "C" at 14383.5,2138.5 h70
  text "PROJECT TITLE:" at 11343.5,277.5 h45
  text ".PRJ_Title" at 11393.5,144.17 h70
  text "DESIGNED FOR:" at 11343.5,-23.5 h45
  text ".PRJ_Customer" at 11393.5,-163.5 h70
  text "D" at -416.5,-231.5 h70
  text "D" at 14383.5,-231.5 h70
  text "FILE NAME:" at 11343.5,-323.5 h45
  text ".PCB_File_Name_No_Path" at 11393.5,-443.5 h70
  text "Texas Instruments (TI) and/or its licensors do not warrant the accuracy or completeness of this specification" at 6374,-605.34 h45
  text "ENGINEER:" at 11343.5,-613.5 h45
  text "LAYOUT BY:" at 12848.5,-613.5 h45
  text "or any information contained therein. TI and/or its licensors do not warrant that this design will meet" at 6329.01,-718 h45
  text ".PRJ_Engineer" at 11393.5,-768.49 h70
  text ".PCB_Layout" at 12899,-768.49 h70
  text "the specifications, will be suitable for your application or fit for any particular purpose, or will operate in" at 6329.01,-830.67 h45
  text ".Layer_Name" at 577,-858.49 h60
  text "ALTIUM DESIGNER VERSION:" at 12848.5,-923.5 h45
  text "an implementation. TI and/or its licensors do not warrant that the design is production worthy. You should" at 6329.01,-943.33 h45
  text "completely validate and test your design implementation to confirm the system functionality for your application." at 6374,-1056 h45
  text ".print_Scale" at 11393.5,-1056.83 h70
  text ".Application_BuildNumber" at 12899,-1056.83 h70
  text "1" at 739.84,-1263.5 h70
  text "2" at 3235.5,-1263.5 h70
  text "3" at 5724.84,-1263.5 h70
  text "4" at 8231.51,-1263.5 h70
  text "5" at 10730.5,-1263.5 h70
  text "6" at 13235.5,-1263.5 h70
M10 Fab Notes:
  drawing of 189 lines, arcs and shapes, not listed
  text "DESIGN INFORMATION" at 12381.02,6028 h60
  text "MIN. TRACK WIDTH:" at 11736.46,5848 h60
  text "8" at 12832.7,5848 h60
  text "MIL" at 12987.46,5848 h60
  text "MIN. CLEARANCE:" at 11736.46,5716 h60
  text "0.2" at 12772.7,5716 h60
  text "mm" at 12987.46,5716 h60
  text "MIN. VIA PAD SIZE:" at 11736.46,5584 h60
  text "24" at 12802.71,5584 h60
  text "MIL" at 12987.46,5584 h60
  text "0.05mm (2MIL)" at 12431.46,5442.29 h60
  text "MINIMUM ANNULAR RING" at 11407.23,5438 h60
  text "EXTERNAL" at 13139.46,5438 h60
  text "PER" at 11607.23,5320 h60
  text "IPC-D-275 CLASS 2 LEVEL C" at 11827.23,5320 h60
  text "MIL, HOLES" at 13315.46,5207.71 h60
  text "+/-" at 12923,5207 h60
  text "+/-" at 13777,5207 h60
  text "REGISTRATION TOLERANCES:" at 11407.23,5202 h60
  text "METAL" at 12607,5202 h60
  text "5" at 13183.2,5202 h60
  text "3" at 14016.2,5202 h60
  text "MIL" at 14132.46,5202 h60
  text "+/-" at 13777,5089 h60
  text "HOLE SIZE TOLERANCE (UNLESS OTHERWISE SPECIFIED):" at 11407.23,5084 h60
  text "3" at 14016.2,5084 h60
  text "MIL" at 14132.46,5084 h60
  text "MATERIAL:" at 11332.46,4874.54 h60
  text "FR-4 High Tg" at 12318.9,4734.21 h60
  text "FR-408" at 11753.46,4725.64 h60
  text "OTHER" at 13241.46,4725.64 h60
  text "X" at 12164,4722 h60
  text "62 MIL (1.6mm) +/-10%" at 12073.56,4562.92 h60
  text "THICKNESS:" at 11407.23,4558.64 h60
  text "X" at 11945.4,4558.64 h60
  text "OTHER" at 13358.46,4558.64 h60
  text "TOLERANCE:" at 11407.23,4400.64 h60
  text "X" at 12246.53,4400.64 h60
  text "ANSI IPC-6012 TYPE 3 CLASS 2" at 12433.48,4400.64 h60
  text "OTHER +/-" at 12433.46,4244.64 h60
  text "BOW & TWIST:" at 11407.23,4087.64 h60
  text "X" at 12246.53,4087.64 h60
  text "ANSI IPC-6012 TYPE 3 CLASS 2" at 12433.48,4087.64 h60
  text "OTHER +/-" at 12433.46,3929.13 h60
  text "DRILLING:" at 11332.46,3790.64 h60
  text "REFERENCE:" at 11407.23,3673.64 h60
  text "X" at 12055.46,3673.64 h60
  text "AS SHOWN" at 12242.46,3673.64 h60
  text "X" at 12956.46,3673.64 h60
  text "NC_DRILL FILES" at 13093.46,3673.64 h60
  text "PTH MIN COPPER THICKNESS:" at 11407.23,3515.64 h60
  text "X" at 12757.46,3515.64 h60
  text "1MIL" at 12894.46,3515.64 h60
  text "OTHER" at 13391.46,3515.64 h60
  text "BOARD FINISH:" at 11332.46,3356.64 h60
  text "SILKSCREEN:" at 11487.68,3238.64 h60
  text "X" at 12436.46,3238.64 h60
  text "TOP" at 12562.46,3238.64 h60
  text "X" at 12946.46,3238.64 h60
  text "BOTTOM" at 13073.46,3238.64 h60
  text "SILKSCREEN COLOR:" at 11487.68,3071.64 h60
  text "X" at 12435.42,3071.64 h60
  text "WHITE" at 12562.46,3071.64 h60
  text "OTHER" at 13073.46,3071.64 h60
  text "X" at 12566.42,2912.44 h60
  text "GREEN" at 12693.46,2912.44 h60
  text "OTHER" at 13311.46,2912.44 h60
  text "SOLDER RESIST COLOR:" at 11487.68,2901.64 h60
  text "X" at 12566.42,2742.44 h60
  text "MATTE" at 12693.46,2742.44 h60
  text "SEMI-GLOSS" at 13311,2741.8 h60
  text "IMMERSION GOLD (ENIG)" at 12393.46,2553.92 h60
  text "ENEPIG" at 13731,2550.64 h60
  text "SURFACE FINISH:" at 11332.46,2549.64 h60
  text "X" at 12206.51,2549.64 h60
  text "IMM. TIN/SILVER OR EQUIV" at 11662,2392.64 h60
  text "OTHER" at 13093.46,2392.64 h60
  text "ARRAY/PANEL:" at 11332.46,2213.64 h60
  text "CUT AND TRIM PER M1 BOARD OUTLINE" at 12393.46,2209.35 h60
  text "N.C. ROUTE" at 12393.46,2057.64 h60
  text "X" at 13072.46,2057.64 h60
  text "V. SCORE" at 13259.46,2057.64 h60
  text "CERTIFICATION:" at 11332.46,1920.64 h60
  text "MATERIALS AND WORKMANSHIP FOR ALL PCBS" at 12057.46,1920.64 h60
  text "TO MEET OR EXCEED THE REQUIREMENTS OF:" at 12057.46,1822.64 h60
  text "X" at 11683.96,1686.13 h60
  text "ANSI IPC-A-600F CLASS ->" at 11822.96,1686.13 h60
  text "X" at 13462.02,1686.13 h60
  text "2" at 13580.96,1686.14 h60
  text "1" at 13265.96,1684.64 h60
  text "3" at 13934.96,1684.64 h60
  text "X" at 11686.02,1526.64 h60
  text "UL 94V-0" at 11822.96,1526.64 h60
  text "X" at 12498.02,1526.64 h60
  text "RoHS" at 12634.96,1526.64 h60
  text "OTHER" at 13279.36,1526.64 h60
  text "PER ORDER" at 13676.42,1526.64 h60
  text "ADDITIONAL REQUIREMENTS:" at 11332.46,1385.64 h60
  text "MICROSECTION:" at 11407.23,1270.64 h60
  text "YES" at 12312.96,1270.64 h60
  text "REQUIRED" at 13174.46,1114.49 h60
  text "BARE BOARD ELEC. TEST:" at 11407.23,1111.64 h60
  text "NONE" at 12712.96,1111.64 h60
  text "X" at 13047.46,1111.64 h60
  text "PER ORDER" at 13766.46,1111.64 h60
  text "MANUFACTURER'S UL:" at 11407.23,954.64 h60
  text "RAIL" at 12572.96,950.35 h60
  text "METAL" at 13064.77,950.35 h60
  text "X" at 13440,950 h60
  text "SILK" at 13576.46,950.35 h60
  text ".Layer_Name" at 577,-858.49 h60
M11 Gerber Information:
  lines w10: -292,-930.17 6308,-930.17 ; -292,-726.83 6310,-726.83 ; -292,-523.5 -292,-1133.5 3713,-1133.5 6310,-1133.5 6310,-523.5 -291.5,-523.5 -291.5,-1133.5 1284,-1133.5 ; 2173,-1133.5 2173,-523.5 ; 3440,-726.83 3440,-523.5 ; 4280,-726.83 4280,-523.5 ; 4902,-1140 4902,-937.17
  text "ALL ARTWORK VIEWED FROM TOP SIDE" at -228.5,-655.67 h60
  text "BOARD #:" at 2248,-655.67 h60
  text ".PRJ_Number" at 2793.5,-655.67 h60
  text "REV:" at 3638,-655.67 h60
  text ".PCB_Rev" at 3929.5,-655.67 h60
  text "SVN REV:" at 4476,-655.67 h60
  text ".VersionControl_RevNumber" at 4982,-655.67 h60
  text "LAYER NAME =" at -228.5,-858.49 h60
  text "TID #:" at 2248,-859 h60
  text ".TID" at 2793.5,-859 h60
  text "PLOT NAME =" at -228.5,-1064.34 h60
  text ".plot_File_Name" at 577,-1064.34 h60
  text "GENERATED    :" at 2250,-1064.34 h60
  text ".Print_Date" at 3119.5,-1064.34 h60
  text ".Print_Time" at 3848.5,-1064.34 h60
  text "TEXAS INSTRUMENTS" at 5113,-1064.34 h60
M12 Stackup:
  drawing of 191 lines, arcs and shapes, not listed
  text "Layer" at 9790.58,7830 h60
  text "Name" at 10200.49,7830 h60
  text "Material" at 11130.23,7830 h60
  text "Thickness" at 11990,7830 h60
  text "Constant" at 12639.84,7830 h60
  text "Board Layer Stack" at 13209.7,7830 h60
  text "1" at 9790.58,7710 h60
  text "Top Overlay" at 10200.49,7710 h60
  text "2" at 9790.58,7590 h60
  text "Top Solder" at 10200.49,7590 h60
  text "Solder Resist" at 11130.23,7590 h60
  text "0.40mil" at 11990,7590 h60
  text "3.5" at 12639.84,7590 h60
  text "3" at 9790.58,7470 h60
  text "Top Layer" at 10200.49,7470 h60
  text "Copper" at 11130.23,7470 h60
  text "1.40mil" at 11990,7470 h60
  text "4" at 9790.58,7350 h60
  text "Dielectric1" at 10200.49,7350 h60
  text "FR-4" at 11130.23,7350 h60
  text "59.20mil" at 11990,7350 h60
  text "4.8" at 12639.84,7350 h60
  text "5" at 9790.58,7230 h60
  text "Bottom Layer" at 10200.49,7230 h60
  text "Copper" at 11130.23,7230 h60
  text "1.40mil" at 11990,7230 h60
  text "6" at 9790.58,7110 h60
  text "Bottom Solder" at 10200.49,7110 h60
  text "Solder Resist" at 11130.23,7110 h60
  text "0.40mil" at 11990,7110 h60
  text "3.5" at 12639.84,7110 h60
  text "7" at 9790.58,6990 h60
  text "Bottom Overlay" at 10200.49,6990 h60
  text ".Layer_Name" at 577,-858.49 h60
M13 Component Bodies Top:
  text ".Layer_Name" at 577,-858.49 h60
M14 Component Bodies Bottom:
  text ".Layer_Name" at 577,-858.49 h60
M15 Courtyards Top:
  text ".Layer_Name" at 577,-858.49 h60
M16 Courtyards Bottom:
  text ".Layer_Name" at 577,-858.49 h60
Drill Drawing:
  circle w1: c5572.72,3071.72 r24.89
  circle w1: c5572.72,2623.76 r14.93
  circle w1: c5572.72,2623.76 r24.89
  lines w1: 5547.83,1702.96 5597.6,1702.96 5597.6,1752.73 5547.83,1752.73 5547.83,1702.96 ; 5547.83,1877.16 5572.72,1852.28 5597.6,1877.16 5572.72,1902.05 5547.83,1877.16 ; 5547.83,2001.6 5547.83,2014.04 5560.27,2026.48 5547.83,2038.93 5547.83,2051.37 5560.27,2051.37 5572.72,2038.93 5585.16,2051.37 5597.6,2051.37 5597.6,2038.93 5585.16,2026.48 5597.6,2014.04 5597.6,2001.6 5585.16,2001.6 5572.72,2014.04 5560.27,2001.6 5547.83,2001.6 ; 5547.83,2163.36 5560.27,2163.36 5560.27,2150.92 5585.16,2150.92 5585.16,2163.36 5597.6,2163.36 5597.6,2188.25 5585.16,2188.25 5585.16,2200.69 5560.27,2200.69 5560.27,2188.25 5547.83,2188.25 5547.83,2163.36 ; 5547.83,2312.68 5560.27,2312.68 5572.72,2300.24 5585.16,2312.68 5597.6,2312.68 5585.16,2325.12 5597.6,2337.57 5585.16,2337.57 5572.72,2350.01 5560.27,2337.57 5547.83,2337.57 5560.27,2325.12 5547.83,2312.68 ; 5547.83,2499.33 5597.6,2499.33 5572.72,2449.56 5547.83,2499.33 ; 5547.83,2760.64 5560.27,2760.64 5572.72,2748.2 5585.16,2760.64 5597.6,2760.64 5585.16,2773.08 5597.6,2785.53 5585.16,2785.53 5572.72,2797.97 5560.27,2785.53 5547.83,2785.53 5560.27,2773.08 5547.83,2760.64 ; 5547.83,2947.29 5597.6,2947.29 5572.72,2897.52 5547.83,2947.29 ; 5547.83,3196.16 5572.72,3208.6 5597.6,3196.16 5585.16,3221.04 5597.6,3245.93 5572.72,3233.49 5547.83,3245.93 5560.27,3221.04 5547.83,3196.16 ; 5557.78,2765.62 5565.25,2765.62 5572.72,2758.15 5580.18,2765.62 5587.65,2765.62 5580.18,2773.08 5587.65,2780.55 5580.18,2780.55 5572.72,2788.01 5565.25,2780.55 5557.78,2780.55 5565.25,2773.08 5557.78,2765.62 ; 5557.78,2937.33 5587.65,2937.33 5572.72,2907.47 5557.78,2937.33
  lines w12: 5480,1658.16 7598.02,1658.16 ; 5480,3300.68 7598.02,3300.68 ; 5850.36,1508.84 5850.36,3450 ; 6207.36,1508.84 6207.36,3450 ; 6868.93,1508.84 6868.93,3450 ; 7153.07,1508.84 7153.07,3450 ; 5480,1508.84 7598.02,1508.84 7598.02,3450 5480,3450 5480,1508.84
  text "Symbol" at 5569.59,3345.48 h72
  text "Quantity" at 5895.16,3345.48 h72
  text "Finished Hole Size" at 6252.16,3345.48 h72
  text "Plated" at 6913.72,3345.48 h72
  text "Hole Type" at 7197.86,3345.48 h72
  text "2" at 5895.16,3196.16 h60
  text "43.31mil (1.100mm)" at 6252.16,3196.16 h60
  text "NPTH" at 6913.72,3196.16 h60
  text "Round" at 7197.86,3196.16 h60
  text "22" at 5895.16,3046.84 h60
  text "7.87mil (0.200mm)" at 6252.16,3046.84 h60
  text "PTH" at 6913.72,3046.84 h60
  text "Round" at 7197.86,3046.84 h60
  text "125" at 5895.16,2897.52 h60
  text "11.81mil (0.300mm)" at 6252.16,2897.52 h60
  text "PTH" at 6913.72,2897.52 h60
  text "Round" at 7197.86,2897.52 h60
  text "246" at 5895.16,2748.2 h60
  text "12.00mil (0.305mm)" at 6252.16,2748.2 h60
  text "PTH" at 6913.72,2748.2 h60
  text "Round" at 7197.86,2748.2 h60
  text "1" at 5895.16,2598.88 h60
  text "30.00mil (0.762mm)" at 6252.16,2598.88 h60
  text "PTH" at 6913.72,2598.88 h60
  text "Round" at 7197.86,2598.88 h60
  text "12" at 5895.16,2449.56 h60
  text "39.37mil (1.000mm)" at 6252.16,2449.56 h60
  text "PTH" at 6913.72,2449.56 h60
  text "Round" at 7197.86,2449.56 h60
  text "20" at 5895.16,2300.24 h60
  text "40.00mil (1.016mm)" at 6252.16,2300.24 h60
  text "PTH" at 6913.72,2300.24 h60
  text "Round" at 7197.86,2300.24 h60
  text "2" at 5895.16,2150.92 h60
  text "43.31mil (1.100mm)" at 6252.16,2150.92 h60
  text "PTH" at 6913.72,2150.92 h60
  text "Round" at 7197.86,2150.92 h60
  text "12" at 5895.16,2001.6 h60
  text "51.18mil (1.300mm)" at 6252.16,2001.6 h60
  text "PTH" at 6913.72,2001.6 h60
  text "Round" at 7197.86,2001.6 h60
  text "3" at 5895.16,1852.28 h60
  text "63.00mil (1.600mm)" at 6252.16,1852.28 h60
  text "PTH" at 6913.72,1852.28 h60
  text "Round" at 7197.86,1852.28 h60
  text "4" at 5895.16,1702.96 h60
  text "125.98mil (3.200mm)" at 6252.16,1702.96 h60
  text "PTH" at 6913.72,1702.96 h60
  text "Round" at 7197.86,1702.96 h60
  text "449 Total" at 5895.16,1553.64 h60
  text ".Layer_Name" at 577,-858.49 h60

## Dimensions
0,-400 to 1000,-400 on M2 Board Dimensions
0,0 to 0,2430 on M2 Board Dimensions
0,0 to 4400,0 on M2 Board Dimensions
